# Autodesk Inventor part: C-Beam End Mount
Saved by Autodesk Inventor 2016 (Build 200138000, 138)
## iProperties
Created: 2015-11
Part Number: C-Beam End Mount
Material: Generic
Document SubType Name: Modeling
Designer: John
Density: 1 g/cm^3
Appearance: Default
Author: John
Revision Number: ANY
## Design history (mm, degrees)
feature "Cut-Extrude2"
body "Solid1"
